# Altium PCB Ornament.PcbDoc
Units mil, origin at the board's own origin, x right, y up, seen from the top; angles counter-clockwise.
Board outline 3000 x 4000 mil, 2 copper layers (Top Layer, Bottom Layer); 12 components, 9 nets, 32 pads, 3 vias.
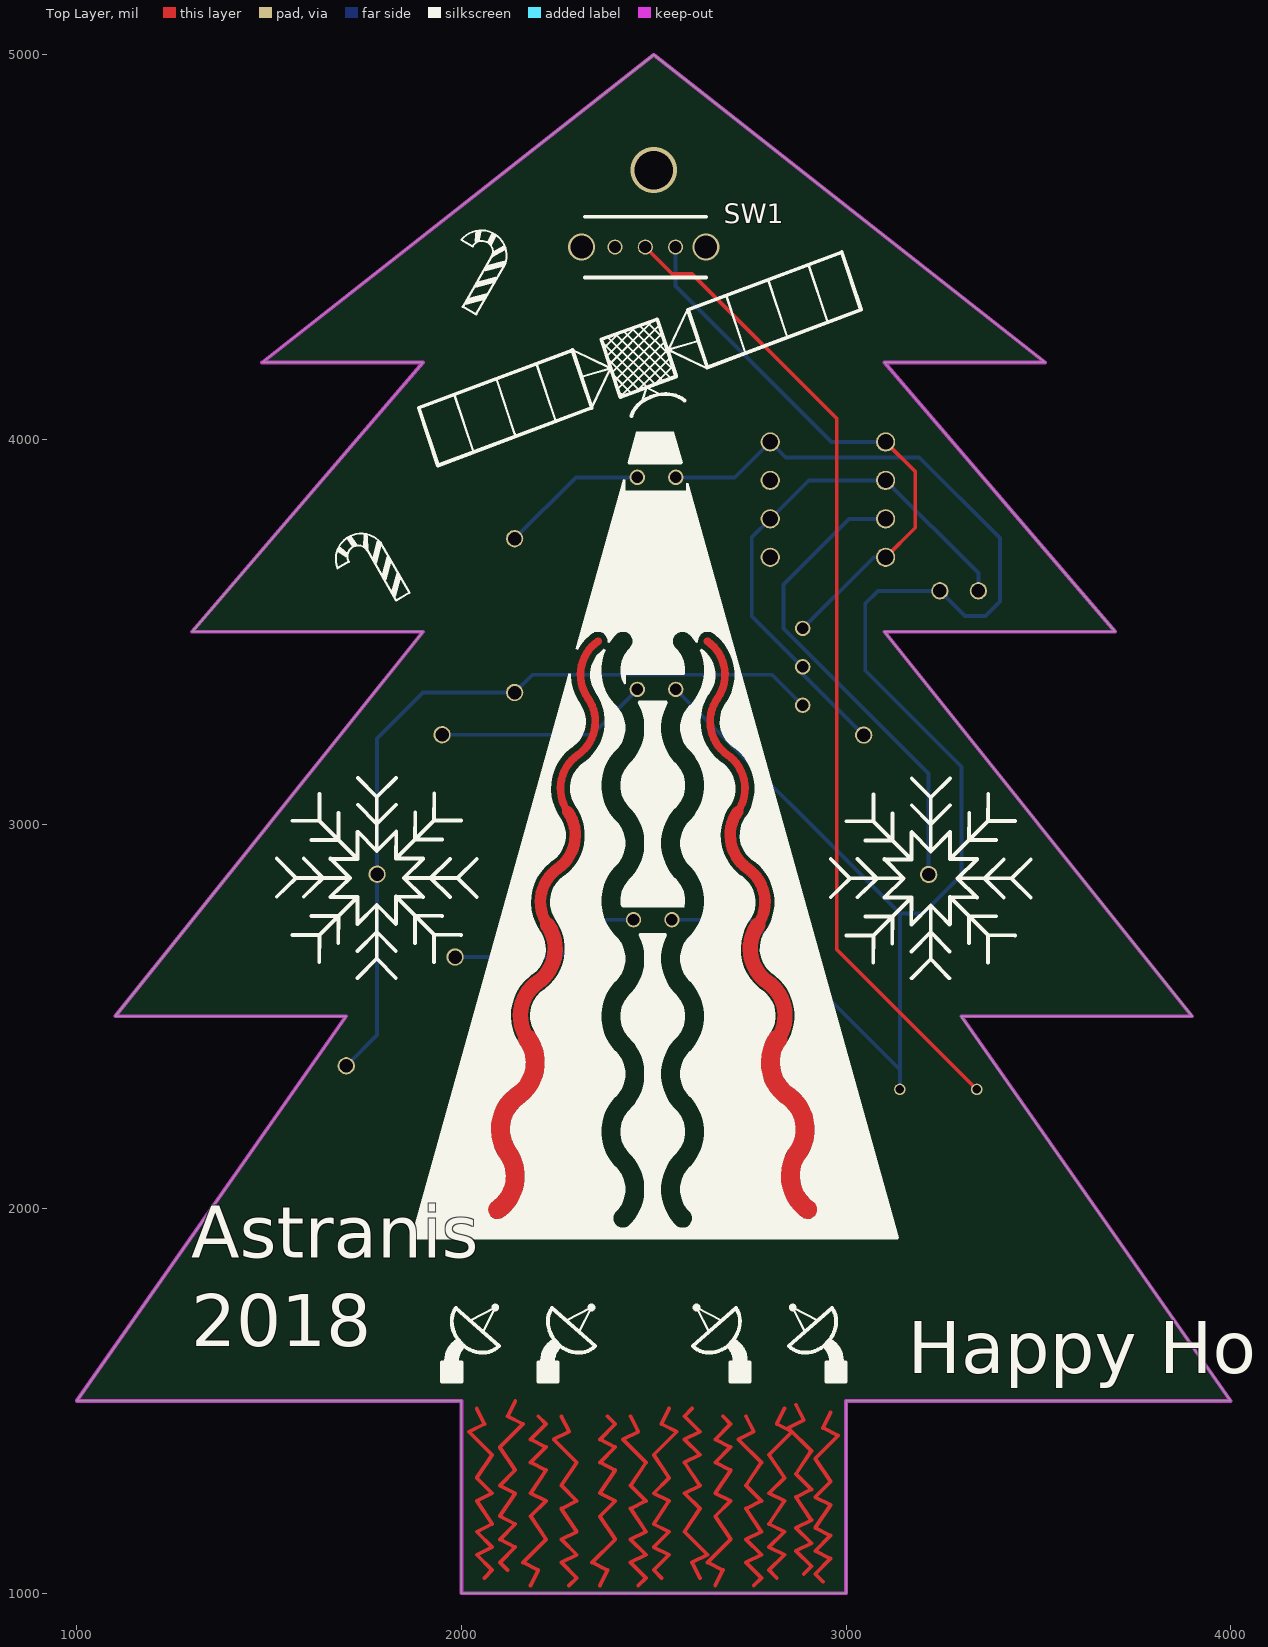
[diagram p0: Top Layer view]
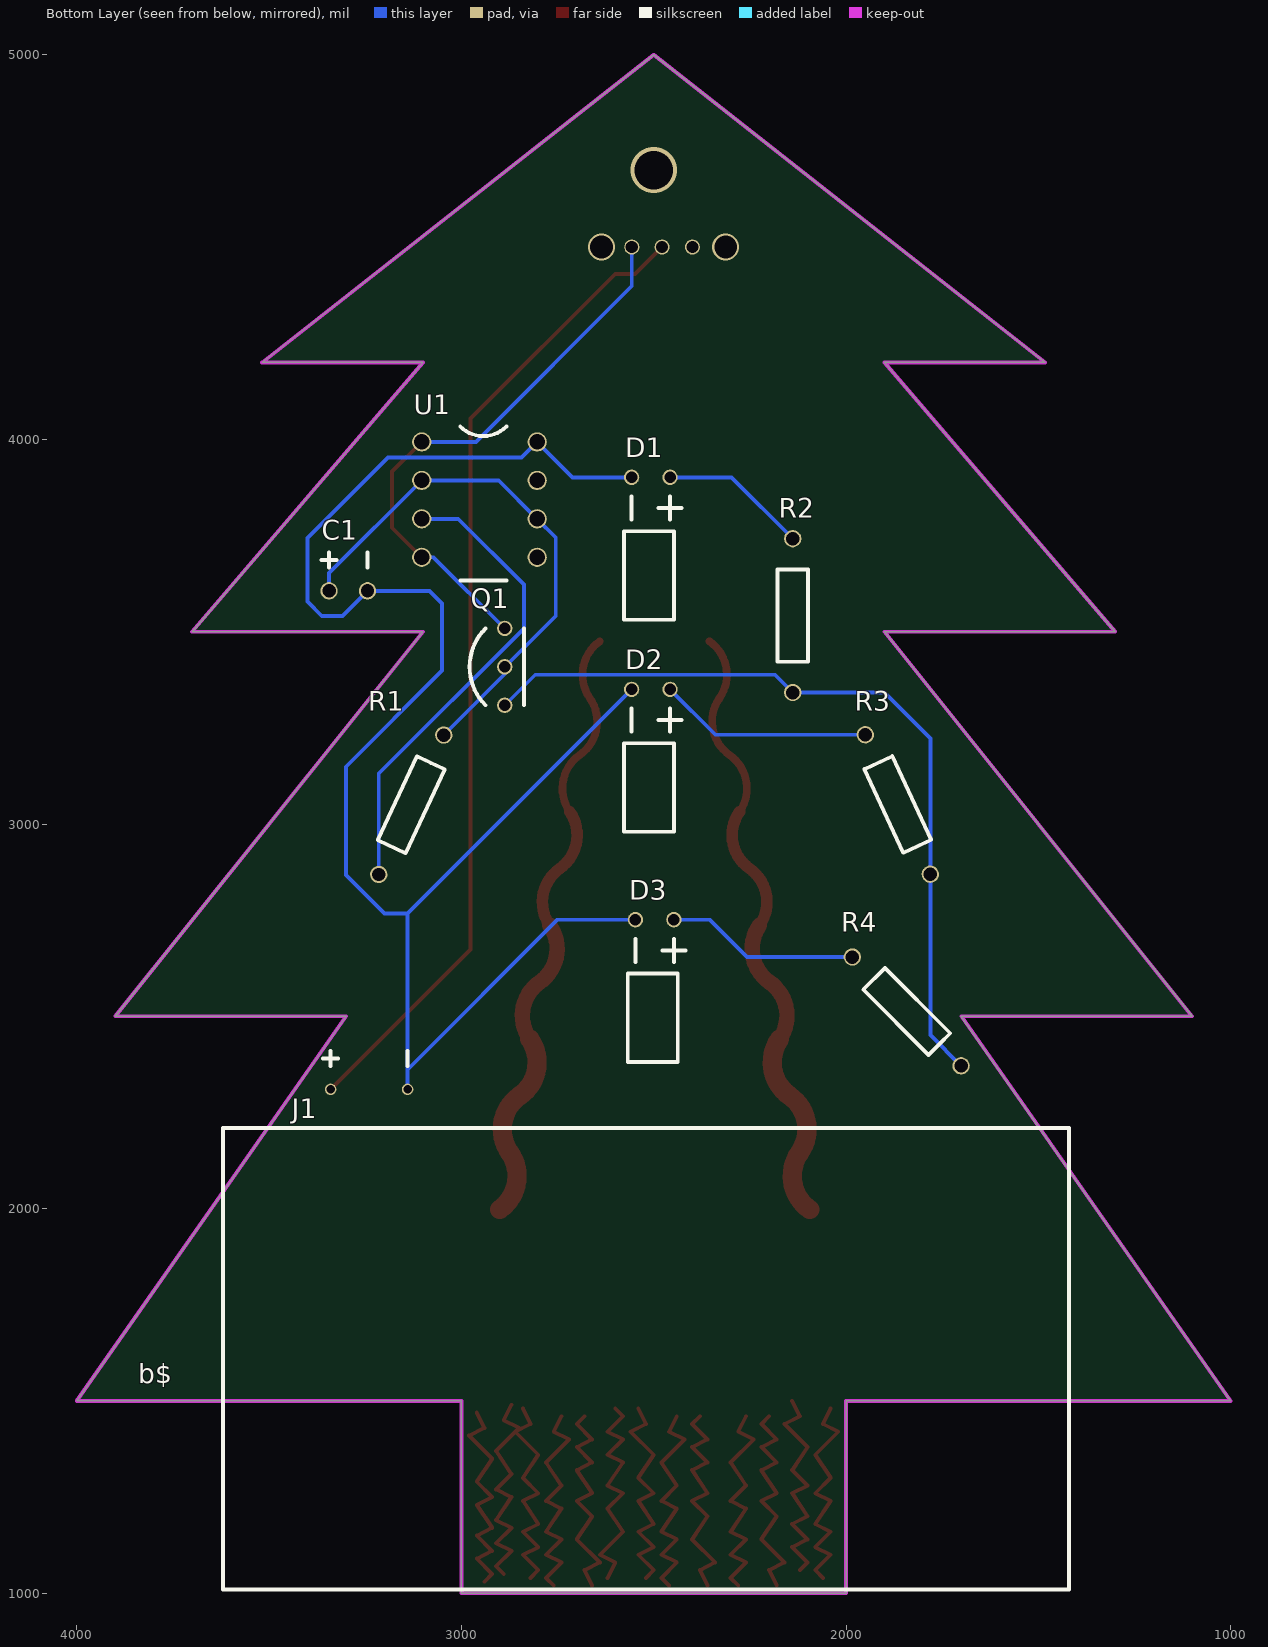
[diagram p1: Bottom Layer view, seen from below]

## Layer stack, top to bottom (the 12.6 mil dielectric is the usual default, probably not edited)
Top Solder: solder mask 0.4, Solder Resist, Dk 3.5
Top Layer: signal copper 1.4
Dielectric 1: dielectric 12.6, FR-4, Dk 4.8
Bottom Layer: signal copper 1.4
Bottom Solder: solder mask 0.4, Solder Resist, Dk 3.5

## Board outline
2000,1000 2000,1500 1000,1500 1700,2500 1100,2500 1900,3500 1300,3500 1900,4200 1481.82,4200 2500,5000 3518.18,4200 3100,4200 3700,3500 3100,3500 3900,2500 3300,2500 4000,1500 3000,1500 3000,1000

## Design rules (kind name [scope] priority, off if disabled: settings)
Clearance EC_SILK [OnLayer('Top Overlay') and InPolygon vs OnTopLayer and IsArc] p1: gap=10 ignorepadtopadclearanceinfootprint=FALSE except(0: Arc-Hole Track-Hole SMDPad-Hole THPad-Hole Via-Hole Fill-Hole Poly-Hole Region-Hole Text-Hole)
Clearance [All] p2: gap=10 ignorepadtopadclearanceinfootprint=FALSE except(0: Arc-Hole Track-Hole SMDPad-Hole THPad-Hole Via-Hole Fill-Hole Poly-Hole Region-Hole Text-Hole)
PolygonConnect [All] p1: connectstyle=Relief reliefconductorwidth=10 reliefentries=4 polygonreliefangle="90 Angle" airgapwidth=10
RoomDefinition Ornament [InComponentClass('Ornament')] p1: confinementstyle=ConfineIn formatcopy=TRUE lockcomponents=FALSE outline 920,700 4380,700 4380,5170 920,5170
RoutingVias [All] p1: holewidth=28 width=50 viastyle="Through Hole" minholewidth=28 minwidth=50 maxholewidth=28 maxwidth=50
SolderMaskExpansion [All] p1: expansion=4
Width [All] p1: maxlimit=100 minlimit=10 preferedwidth=10
30 further rules are at their usual default settings.

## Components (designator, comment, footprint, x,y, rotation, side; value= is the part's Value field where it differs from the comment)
C1 "CAP TH ELECTRO" "CAP ELELCTROLYTIC TH" 3344.07,3606.25 r180 bottom
D1 "Blue LED" BLUE_LED 2457.5,3901.25 r0 bottom
D2 "Blue LED" BLUE_LED 2457.5,3350 r0 bottom
D3 "Blue LED" BLUE_LED 2447.5,2751.25 r0 bottom
J1 "BATT HOLDER 9V" BH9VW 1420,1010 r90 bottom
Q1 "PN2222TA" "BJT NPN" 2887.34,3308.6 r90 bottom
R1 "RES TH" "RES TH" 3045.84,3231.27 r295 bottom
R2 "RES TH" "RES TH" 2138.43,3341.84 r90 bottom
R3 "RES TH" "RES TH" 1780.75,2869.46 r65 bottom
R4 "RES TH" "RES TH" 1700.71,2371.25 r45 bottom
SW1 "OS102011MS2QS1" "SPDT SW" 2635.67,4500 r180 top
U1 "NE555" "555 SOCKET" 3103,3893.36 r180 bottom

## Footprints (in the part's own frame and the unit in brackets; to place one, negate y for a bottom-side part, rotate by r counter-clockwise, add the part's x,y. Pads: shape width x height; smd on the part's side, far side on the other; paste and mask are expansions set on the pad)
"555 SOCKET" [mil] "1-2199298-2"
  round 50 hole 40: 1(0,100) 2(0,0) 3(0,-100) 4(0,-200) 5(300,-200) 6(300,-100) 7(300,0) 8(300,100)
  silkscreen extent 100,-260 220,140
BH9VW [mil] "BH9VPC 9V Battery Holder Leaded"
  round 30 hole 22: 1(1300,1920) 2(1300,1720)
  silkscreen extent 0,0 1400,2200
"BJT NPN" [mil]
  round 40 hole 30: 1(0,0) 2(100,0) 3(200,0)
  silkscreen extent 0,-50 200,91
BLUE_LED [mil]
  round 40 hole 30: 1(0,0) 2(100,0)
  silkscreen extent -30,50 120,370
"CAP ELELCTROLYTIC TH" [mil]
  round 45 hole 35: 1(0,0) 2(100,0)
  silkscreen extent -20,60 100,100
"RES TH" [mil] "RES TH 400MIL"
  round 45 hole 35: 1(0,0) 2(400,0)
  silkscreen extent 80,-40 320,40
"SPDT SW" [mm]
  round 1 hole 0.8: 1(2,0) 2(4,0) 3(6,0)
  silkscreen extent 0,-2 8,2

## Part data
D1 D2 D3: library part Blue_LED, MPN=3474AN-BADB-AGJA-PR-MS
J1: library part BH9VW, "BATTERY HOLDER 9V 6\" LEADS"
Q1: library part "BJT NPN"
SW1: library part "SPDT SW"
U1: MPN=NE555P

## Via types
v1: diameter 70, hole 59.06, Top Layer to Bottom Layer, 2 vias
v2: diameter 120, hole 100, Top Layer to Bottom Layer, 1 vias

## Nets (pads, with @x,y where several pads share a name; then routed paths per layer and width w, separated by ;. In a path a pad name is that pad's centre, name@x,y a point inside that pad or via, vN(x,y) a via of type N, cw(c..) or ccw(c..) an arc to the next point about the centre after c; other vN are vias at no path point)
+9V: Q1.3 SW1.1 U1.1 U1.4 | length 1471.2
  Top Layer w10: U1.4 3180,3770.36 3180,3916.36 U1.1
  Bottom Layer w10: SW1.1 2556.93,4398.73 2962.31,3993.36 U1.1 ; Q1.3 3072.09,3693.36 U1.4
GND: C1.2 D1.2 D2.2 D3.2 J1.2 U1.8 | length 4601.4
  Bottom Layer w10: D3.2 2749.75,2751.25 3140,2361 ; D2.2 3140,2767.5 ; D1.2 2710.89,3901.25 U1.8 2843.36,3953 3190.36,3953 3400,3743.36 3400,3578.19 3363,3541.19 3309.13,3541.19 C1.2 3083.11,3606.25 3050,3573.14 3050,3399 3300,3149 3300,2867.5 3200,2767.5 3140,2767.5 ; J1.2 3140,2361 ; 3140,2361 3140,2767.5
NetC1_1: C1.1 Q1.2 R1.1 U1.2 U1.6 | length 1431
  Bottom Layer w10: R1.1 2887.34,3389.77 Q1.2 2754.75,3541.19 2754.75,3745.11 U1.6 2903,3893.36 U1.2 3344.07,3652.29 C1.1
NetD1_1: D1.1 R2.2 | length 385.1
  Bottom Layer w10: R2.2 2297.85,3901.25 D1.1
NetD2_1: D2.1 R3.2 | length 556.6
  Bottom Layer w10: R3.2 2339.49,3231.99 D2.1
NetD3_1: D3.1 R4.2 | length 504.2
  Bottom Layer w10: R4.2 2257.84,2654.09 2355,2751.25 D3.1
NetJ1_1: J1.1 SW1.2 | length 2577.3
  Top Layer w10: SW1.2 2548.19,4430 2600,4430 2976,4054 2976,2674 J1.1
NetQ1_1: Q1.1 R2.1 R3.1 R4.1 | length 2092.6
  Bottom Layer w10: R4.1 1780.75,2451.28 R3.1 1780.75,3222.58 1900,3341.84 R2.1 2184.71,3388.12 2807.83,3388.12 Q1.1
NetR1_2: R1.2 U1.3 | length 1246.6
  Bottom Layer w10: U1.3 3008.11,3793.36 2837.34,3622.59 2837.34,3508.75 3214.88,3131.2 R1.2
pads on no net: SW1.3 U1.5 U1.7
copper on no net: | length 11790.9
  Top Layer w10: 2040,1480 2060,1440 2020,1420 2080,1360 2040,1300 2080,1260 2040,1240 2080,1180 2040,1160 2080,1120 2040,1100 2080,1060 2060,1040 ; 2120,1060 2100,1080 2140,1120 2100,1140 2140,1180 2100,1200 2140,1260 2100,1280 2140,1320 2100,1380 2160,1440 2120,1460 2140,1500 ; 2180,1020 2200,1060 2160,1080 2220,1140 2180,1200 2220,1240 2180,1260 2220,1320 2180,1340 2220,1380 2180,1400 2220,1440 2200,1460 ; 2260,1460 2280,1420 2240,1400 2300,1340 2260,1280 2300,1240 2260,1220 2300,1160 2260,1140 2300,1100 2260,1080 2300,1040 2280,1020 ; 2360,1020 2380,1060 2340,1080 2400,1140 2360,1200 2400,1240 2360,1260 2400,1320 2360,1340 2400,1380 2360,1400 2400,1440 2380,1460 ; 2440,1460 2460,1420 2420,1400 2480,1340 2440,1280 2480,1240 2440,1220 2480,1160 2440,1140 2480,1100 2440,1080 2480,1040 2460,1020 ; 2520,1040 2500,1060 2540,1100 2500,1120 2540,1160 2500,1180 2540,1240 2500,1260 2540,1300 2500,1360 2560,1420 2520,1440 2540,1480 ; 2600,1480 2580,1460 2620,1420 2580,1400 2620,1360 2580,1340 2620,1280 2580,1260 2620,1220 2580,1160 2640,1100 2600,1080 2620,1040 ; 2660,1020 2680,1060 2640,1080 2700,1140 2660,1200 2700,1240 2660,1260 2700,1320 2660,1340 2700,1380 2660,1400 2700,1440 2680,1460 ; 2740,1460 2760,1420 2720,1400 2780,1340 2740,1280 2780,1240 2740,1220 2780,1160 2740,1140 2780,1100 2740,1080 2780,1040 2760,1020 ; 2820,1040 2800,1060 2840,1100 2800,1120 2840,1160 2800,1180 2840,1240 2800,1260 2840,1300 2800,1360 2860,1420 2820,1440 2840,1480 ; 2870,1490 2890,1450 2850,1430 2910,1370 2870,1310 2910,1270 2870,1250 2910,1190 2870,1170 2910,1130 2870,1110 2910,1070 2890,1050 ; 2940,1030 2920,1050 2960,1090 2920,1110 2960,1150 2920,1170 2960,1230 2920,1250 2960,1290 2920,1350 2980,1410 2940,1430 2960,1470
  Top Layer w20: 2276.86,3031.84 cw(c2363.74,3092.67) 2302.91,3179.56 ccw(c2242.07,3266.44) 2328.95,3327.28 cw(c2415.84,3388.12) 2355,3475 ; 2640,3475 cw(c2579.16,3388.12) 2666.05,3327.28 ccw(c2752.93,3266.44) 2692.09,3179.56 cw(c2631.26,3092.67) 2718.14,3031.84
  Top Layer w30: 2224.76,2736.39 cw(c2311.65,2797.23) 2250.81,2884.12 ccw(c2189.97,2971) 2276.86,3031.84 ; 2718.14,3031.84 ccw(c2805.03,2971) 2744.19,2884.12 cw(c2683.35,2797.23) 2770.24,2736.39
  Top Layer w40: 2172.67,2440.95 cw(c2259.55,2501.79) 2198.72,2588.67 ccw(c2137.88,2675.56) 2224.76,2736.39 ; 2770.24,2736.39 ccw(c2857.12,2675.56) 2796.28,2588.67 cw(c2735.45,2501.79) 2822.33,2440.95
  Top Layer w50: 2094.53,1997.79 ccw(c2033.69,2084.67) 2120.57,2145.51 ; 2120.58,2145.51 cw(c2207.46,2206.35) 2146.62,2293.23 ccw(c2085.79,2380.11) 2172.67,2440.95 ; 2822.33,2440.95 ccw(c2909.21,2380.11) 2848.38,2293.23 cw(c2787.54,2206.35) 2874.42,2145.51 ; 2874.43,2145.51 ccw(c2961.31,2084.67) 2900.47,1997.79
  other v1: 2312.84,4500 2635.67,4500
  other v2: 2500,4700

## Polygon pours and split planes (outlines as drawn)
no net on Top Overlay "NONET_L-01_P-001" (solid): 2041.11,4409.63 2095.75,4424.27 2085.75,4406.95 2031.11,4392.31
no net on Top Overlay "NONET_L-01_P-001" (solid): 2065.91,4452.58 2117.81,4466.49 2107.81,4449.17 2055.91,4435.26
no net on Top Overlay "NONET_L-01_P-001" (solid): 2016.11,4366.33 2073.48,4381.7 2060.75,4363.65 2006.11,4349.01
no net on Top Overlay "NONET_L-01_P-001" (solid): 2081.98,4488.43 2109.34,4503.81 2115.16,4493.89 2073.37,4469.52
no net on Top Overlay "NONET_L-01_P-001" (solid): 2067.49,4513.33 2079.76,4538.58 2091.88,4531.58 2076.62,4501.13
no net on Top Overlay "NONET_L-01_P-001" (solid): 2034.48,4510.34 2037.65,4543.79 2052.24,4542.92 2046.9,4513.67
no net on Top Overlay "NONET_L-01_P-001" (solid): 1702.57,3690.64 1675.19,3710.11 1683.24,3722.31 1705.9,3703.06
no net on Top Overlay "NONET_L-01_P-001" (solid): 1716.49,3720.72 1700.76,3743.97 1712.88,3750.97 1731.62,3722.52
no net on Top Overlay "NONET_L-01_P-001" (solid): 1745.3,3720.82 1745.66,3752.2 1757.16,3752.28 1757.37,3703.91
no net on Top Overlay "NONET_L-01_P-001" (solid): 1818.11,3602.72 1833.48,3660.09 1842.75,3640.04 1828.11,3585.4
no net on Top Overlay "NONET_L-01_P-001" (solid): 1768.31,3688.97 1782.22,3740.88 1792.22,3723.56 1778.31,3671.65
no net on Top Overlay "NONET_L-01_P-001" (solid): 1793.11,3646.02 1807.75,3700.66 1817.75,3683.34 1803.11,3628.7
no net on Top Overlay "NONET_L-01_P-001" (solid): 2610,4118
no net on Top Overlay "NONET_L-01_P-001" (hatched 45Degree grid 20 track 5): 2413.3,4110 2558.05,4163.35 2509,4312 2363.7,4260
no net on Top Overlay "NONET_L-01_P-001" (solid): 2999.36,1550 2949.36,1550 2949.36,1600 2999.36,1600
no net on Top Overlay "NONET_L-01_P-001" (solid): 2961.03,1600.48 2988.21,1600.48 cw(c2988.21,1598.84) 2989.36,1600 ccw(c2925.02,1600) 2970.52,1645.49 2958.17,1657.84 2943.51,1643.18 cw(c2901.21,1600.7) 2961.03,1600.7
no net on Top Overlay "NONET_L-01_P-001" (solid): 2711.03,1600.48 2738.21,1600.48 cw(c2738.21,1598.84) 2739.36,1600 ccw(c2675.02,1600) 2720.52,1645.49 2708.17,1657.84 2693.51,1643.18 cw(c2651.21,1600.7) 2711.03,1600.7
no net on Top Overlay "NONET_L-01_P-001" (solid): 2749.36,1550 2699.36,1550 2699.36,1600 2749.36,1600
no net on Top Overlay "NONET_L-01_P-001" (solid): 2200,1550 2250,1550 2250,1600 2200,1600
no net on Top Overlay "NONET_L-01_P-001" (solid): 2238.33,1600.48 2211.16,1600.48 ccw(c2211.16,1598.84) 2210,1600 cw(c2274.34,1600) 2228.84,1645.49 2241.19,1657.84 2255.86,1643.18 ccw(c2298.16,1600.7) 2238.33,1600.7
no net on Top Overlay "NONET_L-01_P-001" (solid): 1988.33,1600.48 1961.16,1600.48 ccw(c1961.16,1598.84) 1960,1600 cw(c2024.34,1600) 1978.84,1645.49 1991.19,1657.84 2005.86,1643.18 ccw(c2048.16,1600.7) 1988.33,1600.7
no net on Top Overlay "NONET_L-01_P-001" (solid): 1950,1550 2000,1550 2000,1600 1950,1600
no net on Top Overlay "BEAM_LEFT" (solid): 1868.91,1920 2507.5,1920 2507.5,4020 2455.07,4020
no net on Top Overlay "BEAM_RIGHT" (solid): 3138.59,1920 2500,1920 2500,4020 2552.43,4020
no net on Top Solder "NONET_L-01_P-001" (solid): 2413.3,4110 2558.05,4163.35 2509,4312 2363.7,4260

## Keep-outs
Keep-Out Layer:
  the board outline again, w10

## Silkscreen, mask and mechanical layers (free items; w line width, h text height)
Top Overlay:
  drawing of 225 lines, arcs and shapes, not listed
  text "Astranis / 2018" at 1297.42,1598 h230
  text "Happy Holidays!" at 3160.17,1527.44 h230
Bottom Overlay:
  text "b$" at 3840.11,1546.25 h50
Top Solder:
  rectangle: 2000,1000 3000,1500
  lines w20: 2276.86,3031.84 cw(c2363.74,3092.67) 2302.91,3179.56 ccw(c2242.07,3266.44) 2328.95,3327.28 cw(c2415.84,3388.12) 2355,3475 ; 2420,3025 cw(c2495,3100) 2420,3175 ccw(c2345,3250) 2420,3325 cw(c2495,3400) 2420,3475 ; 2575,3025 ccw(c2500,3100) 2575,3175 cw(c2650,3250) 2575,3325 ccw(c2500,3400) 2575,3475 ; 2640,3475 cw(c2579.16,3388.12) 2666.05,3327.28 ccw(c2752.93,3266.44) 2692.09,3179.56 cw(c2631.26,3092.67) 2718.14,3031.84
  lines w30: 2224.76,2736.39 cw(c2311.65,2797.23) 2250.81,2884.12 ccw(c2189.97,2971) 2276.86,3031.84 ; 2420,2725 cw(c2495,2800) 2420,2875 ccw(c2345,2950) 2420,3025 ; 2575,2725 ccw(c2500,2800) 2575,2875 cw(c2650,2950) 2575,3025 ; 2718.14,3031.84 ccw(c2805.03,2971) 2744.19,2884.12 cw(c2683.35,2797.23) 2770.24,2736.39
  lines w40: 2172.67,2440.95 cw(c2259.55,2501.79) 2198.72,2588.67 ccw(c2137.88,2675.56) 2224.76,2736.39 ; 2420,2425 cw(c2495,2500) 2420,2575 ccw(c2345,2650) 2420,2725 ; 2575,2425 ccw(c2500,2500) 2575,2575 cw(c2650,2650) 2575,2725 ; 2770.24,2736.39 ccw(c2857.12,2675.56) 2796.28,2588.67 cw(c2735.45,2501.79) 2822.33,2440.95
  lines w50: 2094.53,1997.79 ccw(c2033.69,2084.67) 2120.57,2145.51 ; 2120.58,2145.51 cw(c2207.46,2206.35) 2146.62,2293.23 ccw(c2085.79,2380.11) 2172.67,2440.95 ; 2420,1975 ccw(c2345,2050) 2420,2125 cw(c2495,2200) 2420,2275 ccw(c2345,2350) 2420,2425 ; 2575,1975 cw(c2650,2050) 2575,2125 ccw(c2500,2200) 2575,2275 cw(c2650,2350) 2575,2425 ; 2822.33,2440.95 ccw(c2909.21,2380.11) 2848.38,2293.23 cw(c2787.54,2206.35) 2874.42,2145.51 ; 2874.43,2145.51 ccw(c2961.31,2084.67) 2900.47,1997.79
Bottom Solder:
  rectangle: 2328.49,3400 2628.49,3851.99
  rectangle: 2350,2850 2650,3301.99
  rectangle: 2350,2250 2650,2701.99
